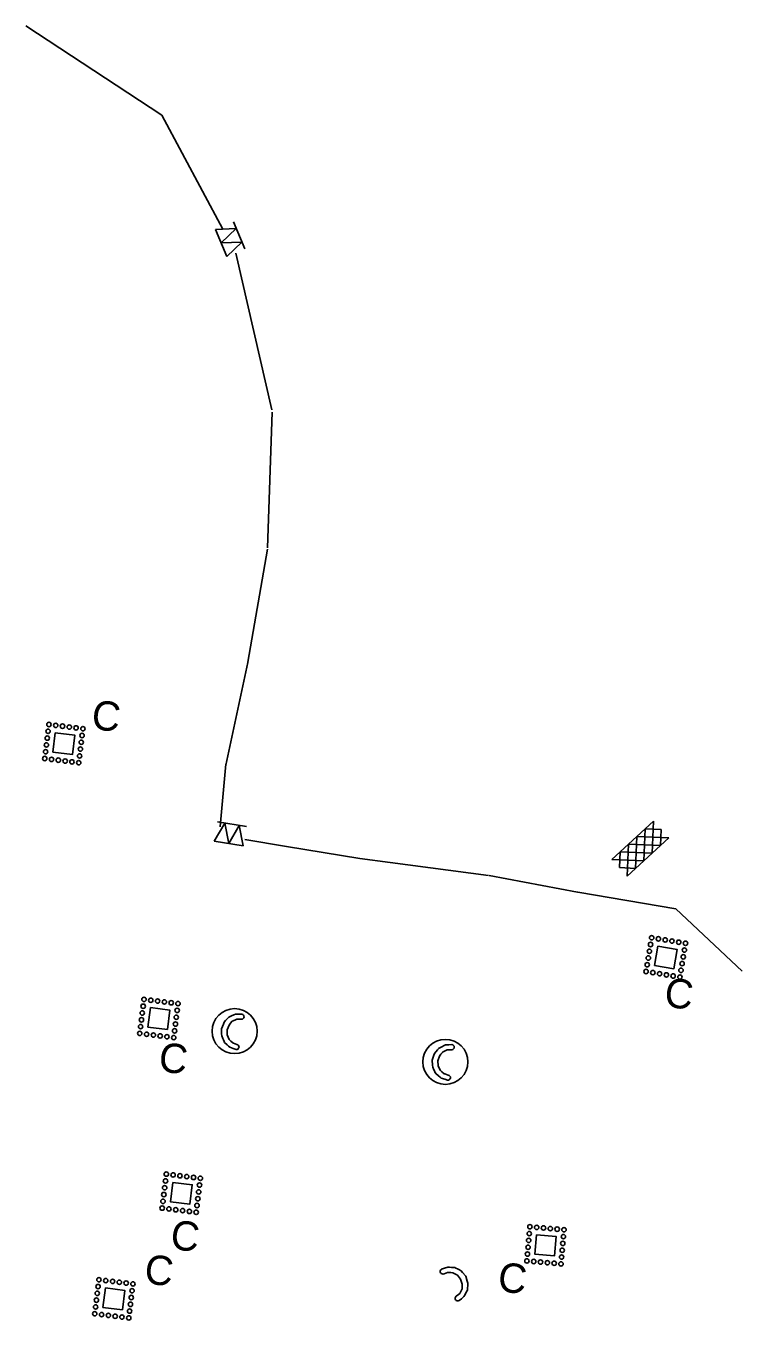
# Model space of a CAD drawing. Extents: x 2470000 to 2520000, y 340000 to 380000.
# Drawn here: x 2483613 to 2483978, y 365690 to 366351 of the extents above; entities that cross this region are included whole.
import ezdxf

# ---------------------------------------------------------------- set-up
doc = ezdxf.new("R2010")
doc.units = 0
for name, color, linetype in [('Coir Fiber Wattle with PAM Both CELL', 7, 'Continuous'), ('Prop Guardrail', 7, 'Continuous'), ('Prop Guardrail Anchor Unit CELL', 7, 'Continuous'), ('Prop Structure Anchor Unit CELL', 7, 'Continuous'), ('Rock Silt Check Type A Both CELL', 7, 'Continuous'), ('Scratch_Level_5', 7, 'Continuous'), ('Sheet Data Field CELL', 7, 'Continuous'), ('Special Sediment Control Fence Section Both CELL', 7, 'Continuous'), ('Temporary Silt Fence CG', 7, 'Continuous'), ('Wattle Both CELL', 7, 'Continuous')]:
    doc.layers.add(name, color=color, linetype=linetype)

# ---------------------------------------------------------------- blocks, each defined once
blk = doc.blocks.new('C3')
at = {"layer": 'Prop Guardrail'}
blk.add_text('C', height=0.3, dxfattribs=at).set_placement((-0.161, -0.136))
blk = doc.blocks.new('C2')
at = {"layer": 'Prop Guardrail Anchor Unit CELL'}
blk.add_text('C', height=0.3, dxfattribs=at).set_placement((-0.161, -0.136))

msp = doc.modelspace()

# ---------------------------------------------------------------- linework, layer by layer
at = {"layer": 'Coir Fiber Wattle with PAM Both CELL'}
for p, q in [((2483716.38, 365840.99), (2483715.49, 365838.51)), ((2483716.38, 365840.99), (2483717.16, 365841.88)), ((2483717.9, 365842.72), (2483717.16, 365841.88)), ((2483717.9, 365842.72), (2483718.05, 365842.89)), ((2483719.38, 365843.48), (2483718.05, 365842.89)), ((2483720.39, 365843.93), (2483719.38, 365843.48)), ((2483721.18, 365843.94), (2483720.39, 365843.93)), ((2483722.73, 365843.96), (2483721.18, 365843.94)), ((2483715.49, 365838.5), (2483715.49, 365838.51)), ((2483715.49, 365838.5), (2483715.5, 365835.96)), ((2483715.5, 365835.96), (2483715.95, 365834.84)), ((2483715.95, 365834.84), (2483716.5, 365833.51)), ((2483716.5, 365833.51), (2483717.26, 365832.82)), ((2483717.26, 365832.82), (2483718.36, 365831.82)), ((2483718.67, 365831.7), (2483718.36, 365831.82)), ((2483718.67, 365831.7), (2483720.42, 365831.06)), ((2483826.78, 365827.77), (2483825.48, 365827.13)), ((2483827.77, 365828.26), (2483826.78, 365827.77)), ((2483828.56, 365828.31), (2483827.77, 365828.26)), ((2483830.11, 365828.39), (2483828.56, 365828.31)), ((2483823.88, 365825.16), (2483823.1, 365822.65)), ((2483823.1, 365822.63), (2483823.1, 365822.65)), ((2483823.1, 365822.63), (2483823.21, 365820.1)), ((2483823.88, 365825.16), (2483824.63, 365826.09)), ((2483825.33, 365826.95), (2483824.63, 365826.09)), ((2483825.33, 365826.95), (2483825.48, 365827.13)), ((2483823.21, 365820.1), (2483823.72, 365819)), ((2483823.72, 365819), (2483824.32, 365817.69)), ((2483824.32, 365817.69), (2483825.11, 365817.03)), ((2483825.11, 365817.03), (2483826.25, 365816.08)), ((2483826.56, 365815.98), (2483826.25, 365816.08)), ((2483826.56, 365815.98), (2483828.33, 365815.41))]:
    msp.add_line(p, q, dxfattribs=at)
for points in [[(2483719.99, 365828.5), (2483718.52, 365829.02), (2483716.8, 365829.62), (2483716.18, 365830.18), (2483715.43, 365830.86), (2483714.1, 365832.06), (2483714.09, 365832.1), (2483713.91, 365832.5), (2483713.88, 365832.57), (2483713.49, 365833.45), (2483713.23, 365834.06), (2483712.64, 365835.4), (2483712.62, 365836.44), (2483712.56, 365838.99), (2483712.56, 365839), (2483713.48, 365841.48), (2483713.84, 365842.44), (2483714.61, 365843.27), (2483714.77, 365843.44), (2483715.43, 365844.14), (2483715.93, 365844.68), (2483716.04, 365844.8), (2483716.29, 365845.07), (2483716.3, 365845.08), (2483717.69, 365845.67), (2483718.92, 365846.2), (2483719.67, 365846.52), (2483721.42, 365846.57), (2483722.97, 365846.61)], [(2483828.01, 365812.83), (2483826.52, 365813.29), (2483824.78, 365813.82), (2483824.14, 365814.35), (2483823.36, 365815), (2483821.98, 365816.14), (2483821.96, 365816.18), (2483821.77, 365816.58), (2483821.74, 365816.64), (2483821.32, 365817.5), (2483821.02, 365818.1), (2483820.38, 365819.42), (2483820.31, 365820.46), (2483820.15, 365823), (2483820.16, 365823.01), (2483820.97, 365825.52), (2483821.28, 365826.5), (2483822.02, 365827.36), (2483822.18, 365827.54), (2483822.8, 365828.27), (2483823.28, 365828.83), (2483823.39, 365828.95), (2483823.63, 365829.23), (2483823.64, 365829.24), (2483825, 365829.89), (2483826.21, 365830.47), (2483826.94, 365830.82), (2483828.69, 365830.94), (2483830.24, 365831.05)]]:
    msp.add_lwpolyline(points, dxfattribs=at)
for centre in [(2483719.24, 365837.86), (2483826.87, 365822.15)]:
    msp.add_circle(centre, 11.5, dxfattribs=at)
for centre, radius, start, end in [((2483722.75, 365845.29), 1.33, 269.37322, 80.48586), ((2483720.2, 365829.78), 1.3, 260.48586, 80.48586), ((2483830.07, 365829.72), 1.33, 271.75943, 82.87207), ((2483828.17, 365814.12), 1.3, 262.87207, 82.87207)]:
    msp.add_arc(centre, radius, start, end, dxfattribs=at)
at = {"layer": 'Prop Structure Anchor Unit CELL'}
for points in [[(2483687.63, 365760.62), (2483697.56, 365759.4), (2483696.34, 365749.47), (2483686.42, 365750.7)], [(2483873.43, 365733.84), (2483883.39, 365732.96), (2483882.52, 365723), (2483872.56, 365723.89)], [(2483653.22, 365706.67), (2483663.15, 365705.45), (2483661.93, 365695.52), (2483652, 365696.75)]]:
    msp.add_lwpolyline(points, close=True, dxfattribs=at)
for centre in [(2483683.94, 365761.34), (2483684.36, 365764.82), (2483687.84, 365764.39), (2483691.31, 365763.96), (2483694.79, 365763.54), (2483698.26, 365763.11), (2483701.73, 365762.68), (2483683.08, 365754.39), (2483683.51, 365757.87), (2483700.88, 365755.74), (2483701.31, 365759.21), (2483682.23, 365747.45), (2483682.66, 365750.92), (2483700.03, 365748.79), (2483700.45, 365752.26), (2483685.7, 365747.02), (2483689.18, 365746.59), (2483692.65, 365746.17), (2483696.13, 365745.74), (2483699.6, 365745.31), (2483869.71, 365734.43), (2483870.02, 365737.92), (2483873.5, 365737.61), (2483876.99, 365737.31), (2483880.48, 365737), (2483883.96, 365736.7), (2483887.45, 365736.39), (2483869.1, 365727.46), (2483869.41, 365730.94), (2483886.84, 365729.42), (2483887.14, 365732.91), (2483868.79, 365723.97), (2483886.23, 365722.44), (2483886.53, 365725.93), (2483868.49, 365720.48), (2483871.98, 365720.18), (2483875.46, 365719.87), (2483878.95, 365719.57), (2483882.44, 365719.26), (2483885.92, 365718.96), (2483649.95, 365710.86), (2483653.42, 365710.44), (2483656.9, 365710.01), (2483660.37, 365709.58), (2483663.85, 365709.16), (2483667.32, 365708.73), (2483649.1, 365703.92), (2483649.52, 365707.39), (2483666.47, 365701.78), (2483666.89, 365705.26), (2483648.24, 365696.97), (2483648.67, 365700.44), (2483665.61, 365694.83), (2483666.04, 365698.31), (2483647.82, 365693.49), (2483651.29, 365693.07), (2483654.77, 365692.64), (2483658.24, 365692.21), (2483661.71, 365691.79), (2483665.19, 365691.36)]:
    msp.add_circle(centre, 1.12, dxfattribs=at)
at = {"layer": 'Rock Silt Check Type A Both CELL'}
for p, q in [((2483911.86, 365925.62), (2483933.14, 365945.17)), ((2483928.86, 365941.26), (2483928.18, 365924.93)), ((2483937.04, 365940.95), (2483928.86, 365941.26)), ((2483933.14, 365945.17), (2483932.45, 365928.85)), ((2483937.04, 365940.95), (2483936.68, 365932.74)), ((2483919.67, 365917.11), (2483940.95, 365936.67)), ((2483924.63, 365937.36), (2483923.91, 365921)), ((2483940.95, 365936.67), (2483924.63, 365937.36)), ((2483916.09, 365929.44), (2483915.74, 365921.38)), ((2483932.45, 365928.85), (2483916.09, 365929.51)), ((2483920.36, 365933.43), (2483919.67, 365917.11)), ((2483936.68, 365932.74), (2483920.36, 365933.43)), ((2483928.18, 365924.93), (2483911.86, 365925.62)), ((2483923.91, 365921), (2483915.74, 365921.38))]:
    msp.add_line(p, q, dxfattribs=at)
at = {"layer": 'Scratch_Level_5'}
for points in [[(2483627.67, 365990.3), (2483637.59, 365989.08), (2483636.37, 365979.16), (2483626.45, 365980.39)], [(2483935.31, 365881.25), (2483945.18, 365879.63), (2483943.55, 365869.76), (2483933.69, 365871.4)], [(2483676.22, 365849.87), (2483686.15, 365848.63), (2483684.91, 365838.71), (2483674.99, 365839.96)]]:
    msp.add_lwpolyline(points, close=True, dxfattribs=at)
for centre in [(2483624.4, 365994.5), (2483627.87, 365994.07), (2483631.34, 365993.65), (2483634.82, 365993.22), (2483638.29, 365992.79), (2483641.77, 365992.37), (2483623.54, 365987.55), (2483623.97, 365991.03), (2483640.91, 365985.42), (2483641.34, 365988.89), (2483622.69, 365980.6), (2483623.12, 365984.08), (2483640.49, 365981.94), (2483622.26, 365977.13), (2483625.74, 365976.7), (2483629.21, 365976.28), (2483632.69, 365975.85), (2483636.16, 365975.42), (2483639.63, 365975), (2483640.06, 365978.47), (2483931.65, 365882.13), (2483932.22, 365885.58), (2483935.67, 365885.01), (2483939.13, 365884.44), (2483942.58, 365883.87), (2483946.03, 365883.3), (2483949.49, 365882.73), (2483930.51, 365875.22), (2483931.08, 365878.68), (2483948.35, 365875.83), (2483948.92, 365879.28), (2483929.37, 365868.32), (2483929.94, 365871.77), (2483932.82, 365867.75), (2483936.28, 365867.18), (2483939.73, 365866.61), (2483947.21, 365868.92), (2483947.78, 365872.37), (2483943.18, 365866.04), (2483946.64, 365865.47), (2483672.96, 365854.07), (2483676.43, 365853.64), (2483679.91, 365853.21), (2483672.09, 365847.13), (2483672.53, 365850.6), (2483683.38, 365852.77), (2483686.85, 365852.34), (2483689.89, 365848.44), (2483690.33, 365851.91), (2483671.23, 365840.18), (2483671.66, 365843.65), (2483689.03, 365841.49), (2483689.46, 365844.96), (2483670.79, 365836.71), (2483674.27, 365836.27), (2483677.74, 365835.84), (2483681.21, 365835.41), (2483684.69, 365834.98), (2483688.16, 365834.54), (2483688.59, 365838.02)]:
    msp.add_circle(centre, 1.12, dxfattribs=at)
at = {"layer": 'Sheet Data Field CELL'}
for p, q in [((2483682, 366305.8), (2483612.64, 366351.4)), ((2483713.19, 366247.62), (2483682, 366305.8)), ((2483738.2, 366155.32), (2483719.85, 366235.21)), ((2483736.02, 366084.75), (2483738.33, 366154.03)), ((2483725.95, 366026.39), (2483735.95, 366084.07)), ((2483725.92, 366026.21), (2483714.74, 365973.74)), ((2483714.83, 365974.33), (2483711.94, 365942.47)), ((2483724.47, 365935.69), (2483745.8, 365932.15)), ((2483745.77, 365932.15), (2483783.22, 365926.12)), ((2483783.12, 365926.13), (2483798.66, 365923.96)), ((2483798.62, 365923.97), (2483848.9, 365917.4)), ((2483849.18, 365917.36), (2483894.4, 365908.84))]:
    msp.add_line(p, q, dxfattribs=at)
msp.add_lwpolyline([(2483894.47, 365908.82), (2483944.62, 365900.33), (2483978.41, 365868.48)], dxfattribs=at)
at = {"layer": 'Special Sediment Control Fence Section Both CELL'}
for p, q in [((2483718.61, 366251.34), (2483724.46, 366237.53)), ((2483709.4, 366247.44), (2483715.25, 366233.63)), ((2483710.51, 365944.8), (2483725.3, 365942.32)), ((2483708.85, 365934.93), (2483723.65, 365932.45))]:
    msp.add_line(p, q, dxfattribs=at)
for points in [[(2483709.4, 366247.44), (2483720.07, 366247.89), (2483712.32, 366240.53)], [(2483712.32, 366240.53), (2483722.99, 366240.98), (2483715.25, 366233.63)], [(2483708.85, 365934.93), (2483714.21, 365944.18), (2483716.25, 365933.69)], [(2483716.25, 365933.69), (2483721.6, 365942.94), (2483723.65, 365932.45)]]:
    msp.add_lwpolyline(points, dxfattribs=at)
at = {"layer": 'Temporary Silt Fence CG'}
msp.add_arc((2483716.92, 365942.02), 5, 174.81862, 177.75136, dxfattribs=at)
at = {"layer": 'Wattle Both CELL'}
for p, q in [((2483827.94, 365714.53), (2483826.17, 365713.95)), ((2483827.94, 365714.53), (2483828.26, 365714.63)), ((2483829.73, 365714.53), (2483828.26, 365714.63)), ((2483830.76, 365714.46), (2483829.73, 365714.53)), ((2483832.02, 365713.75), (2483830.76, 365714.46)), ((2483833.07, 365713.17), (2483832.02, 365713.75)), ((2483834.65, 365711.18), (2483833.07, 365713.17)), ((2483834.65, 365711.18), (2483834.66, 365711.17)), ((2483835.51, 365708.68), (2483834.66, 365711.17)), ((2483835.51, 365708.68), (2483835.45, 365707.49)), ((2483832.38, 365702.4), (2483833.58, 365703.38)), ((2483833.58, 365703.38), (2483834.19, 365703.88)), ((2483834.19, 365703.88), (2483834.71, 365704.86)), ((2483834.71, 365704.86), (2483835.38, 365706.15)), ((2483835.39, 365706.38), (2483835.38, 365706.15)), ((2483835.39, 365706.38), (2483835.45, 365707.49))]:
    msp.add_line(p, q, dxfattribs=at)
msp.add_lwpolyline([(2483824.92, 365716.22), (2483826.39, 365716.73), (2483828.11, 365717.32), (2483828.94, 365717.27), (2483829.95, 365717.2), (2483831.74, 365717.09), (2483831.78, 365717.07), (2483832.17, 365716.86), (2483832.23, 365716.83), (2483833.08, 365716.38), (2483833.67, 365716.07), (2483834.96, 365715.38), (2483835.63, 365714.58), (2483837.25, 365712.62), (2483837.26, 365712.61), (2483838.08, 365710.1), (2483838.4, 365709.12), (2483838.31, 365707.99), (2483838.29, 365707.76), (2483838.21, 365706.8), (2483838.15, 365706.07), (2483838.14, 365705.9), (2483838.11, 365705.53), (2483838.11, 365705.53), (2483837.39, 365704.2), (2483836.76, 365703.01), (2483836.37, 365702.3), (2483835.03, 365701.17), (2483833.84, 365700.18)], dxfattribs=at)
for centre, radius, start in [((2483825.54, 365715.08), 1.3, 118.92524), ((2483833.19, 365701.35), 1.33, 127.8126)]:
    msp.add_arc(centre, radius, start, 298.92524, dxfattribs=at)

# ---------------------------------------------------------------- block references
at = {"layer": 'Prop Guardrail', "xscale": 50, "yscale": 50, "rotation": -7.100872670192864}
msp.add_blockref('C3', (2483688.71, 365823.21), dxfattribs=at)
at = {"layer": 'Prop Structure Anchor Unit CELL'}
for p, xscale, yscale, rotation in [((2483694.74, 365732.47), 49.99999999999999, 50.00000000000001, -6.997703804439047), ((2483681.43, 365714.91), 49.99999999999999, 50.00000000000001, -6.997703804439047), ((2483861.91, 365710.92), 50.00000000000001, 49.99999999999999, -6.997703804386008)]:
    msp.add_blockref('C2', p, dxfattribs=dict(at, xscale=xscale, yscale=yscale, rotation=rotation))
at = {"layer": 'Scratch_Level_5', "xscale": 49.99999999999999, "yscale": 50.00000000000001, "rotation": -6.997703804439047}
for p in [(2483654.42, 365998.11), (2483946.97, 365856.22)]:
    msp.add_blockref('C3', p, dxfattribs=at)

doc.saveas('drawing.dxf')
